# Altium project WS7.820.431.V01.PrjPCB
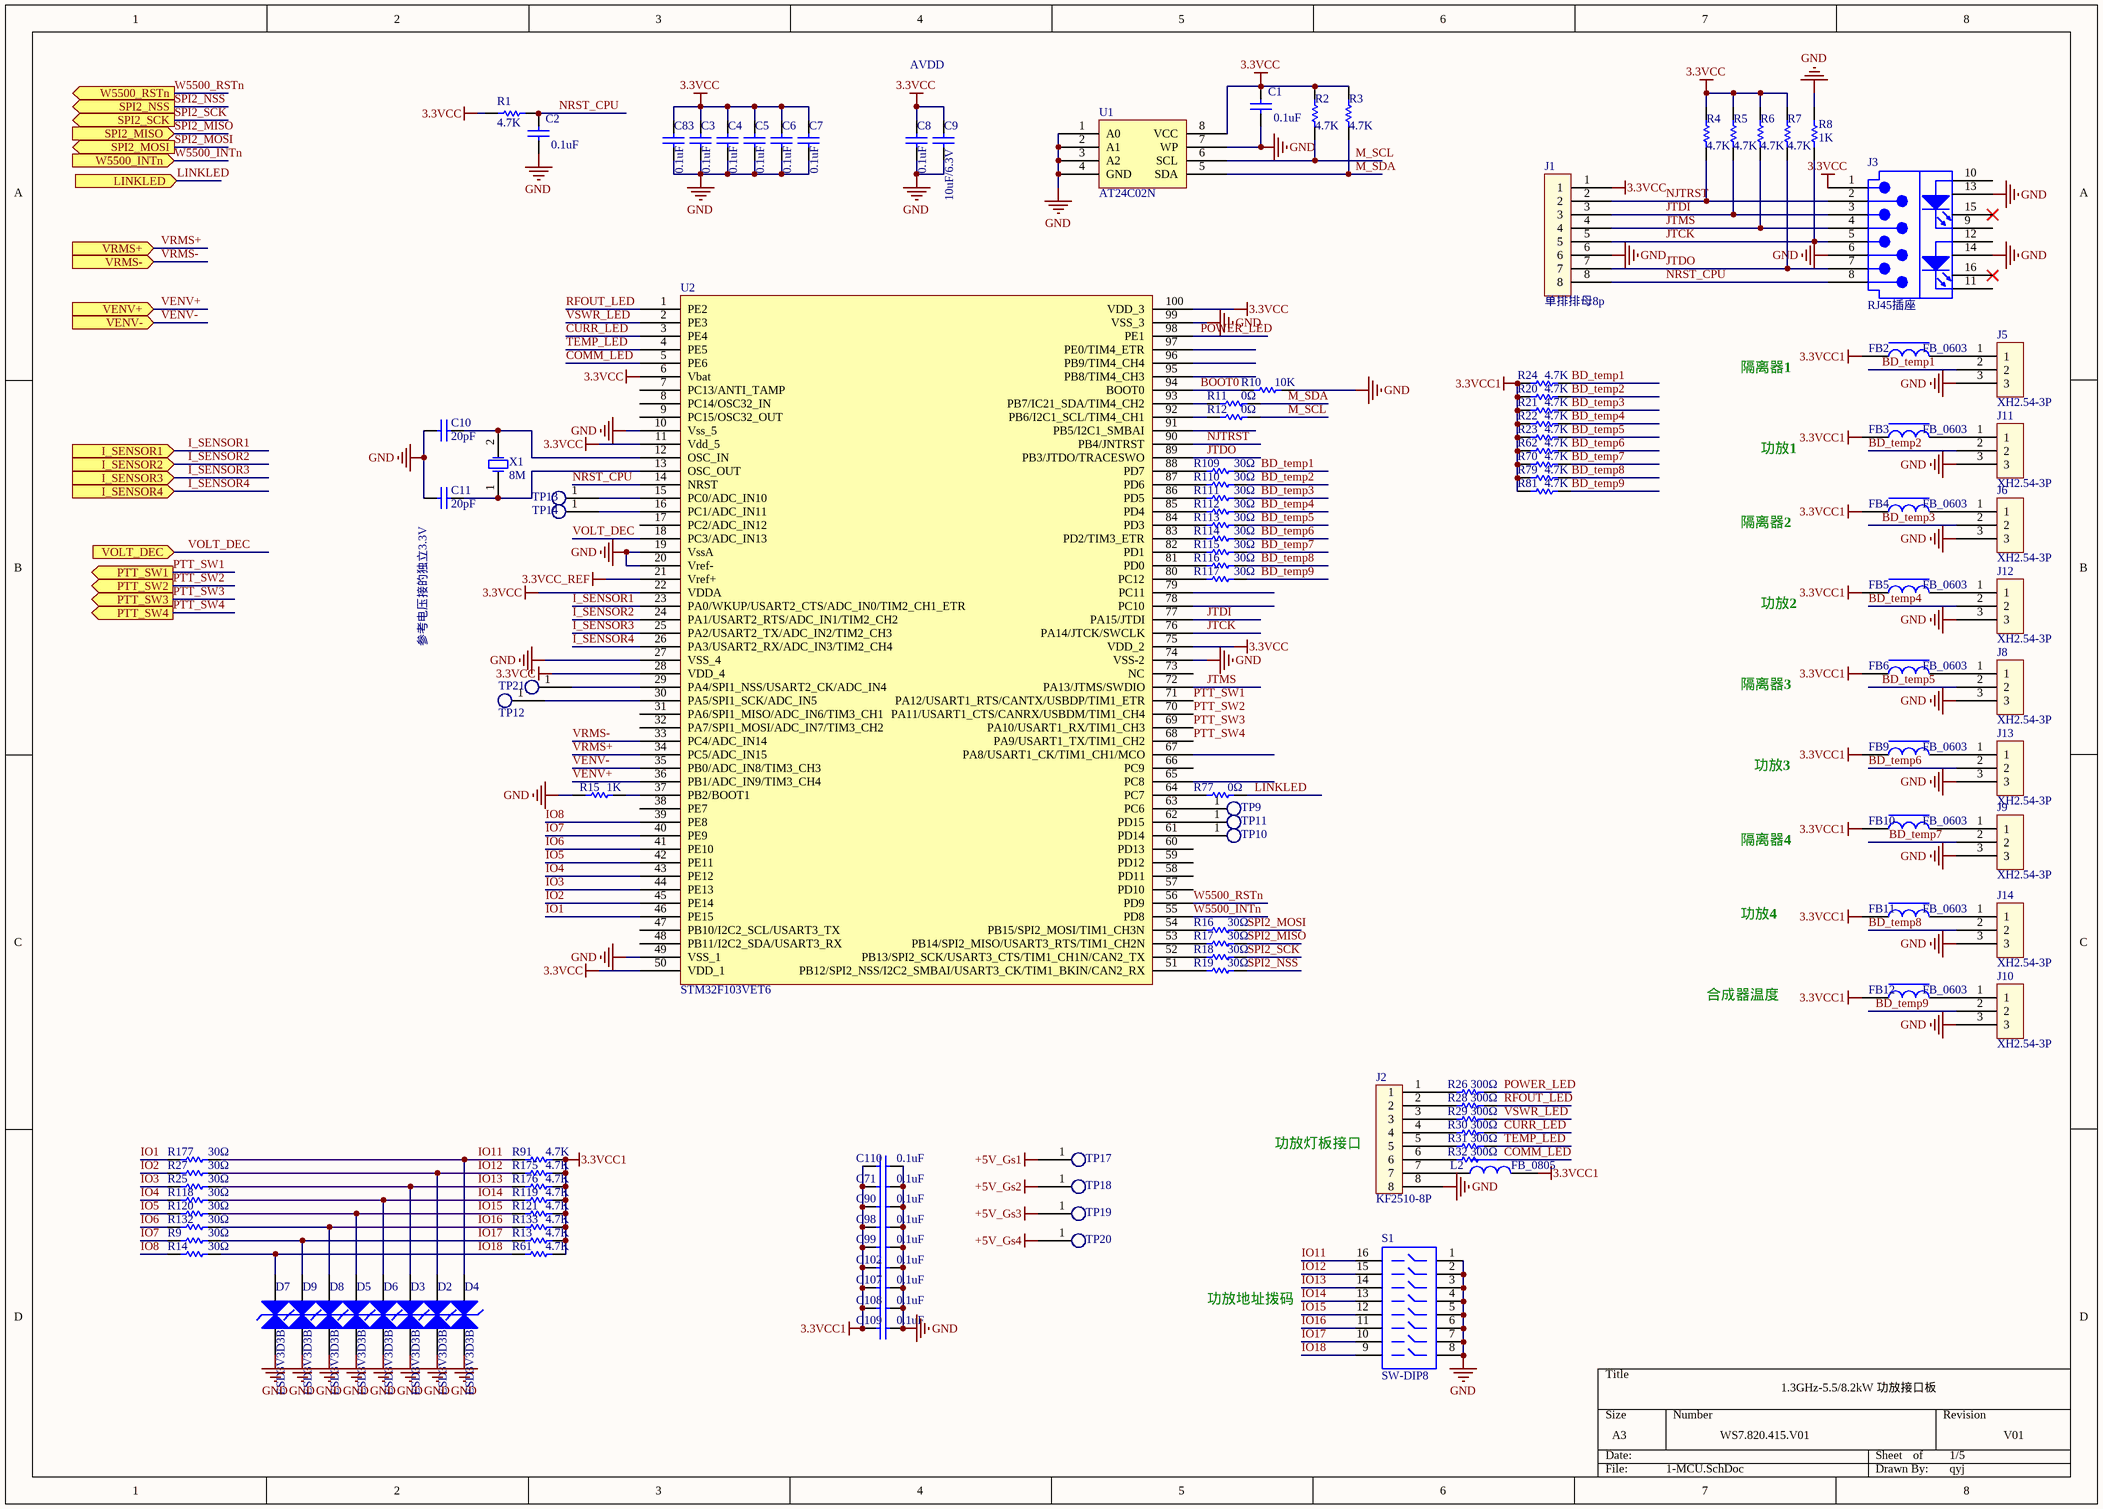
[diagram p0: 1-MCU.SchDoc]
4 sheets, 379 parts. Net scope: flat (ports and power ports of the same name join across sheets).
Board files: WS7.820.431.V01.PcbDoc, 功放插件尺寸图.PcbDoc
Sheets:
  1-MCU.SchDoc
  2-RJ45.SchDoc
  3-RF.SchDoc
  4-POWER.SchDoc

## Sheet 1-MCU.SchDoc
size A3

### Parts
C1  0.1uF  [C0603]
C2  0.1uF  [C0603]
C3  0.1uF  [C0603]
C4  0.1uF  [C0603]
C5  0.1uF  [C0603]
C6  0.1uF  [C0603]
C7  0.1uF  [C0603]
C8  0.1uF  [C0603]
C9  10uF/6.3V  [C0603]
C10  20pF  [C0603]
C11  20pF  [C0603]
C71  0.1uF  [C0603]
C83  0.1uF  [C0603]
C90  0.1uF  [C0603]
C98  0.1uF  [C0603]
C99  0.1uF  [C0603]
C102  0.1uF  [C0603]
C107  0.1uF  [C0603]
C108  0.1uF  [C0603]
C109  0.1uF  [C0603]
C110  0.1uF  [C0603]
D2  ESD3V3D3B  [SOD-323]
D3  ESD3V3D3B  [SOD-323]
D4  ESD3V3D3B  [SOD-323]
D5  ESD3V3D3B  [SOD-323]
D6  ESD3V3D3B  [SOD-323]
D7  ESD3V3D3B  [SOD-323]
D8  ESD3V3D3B  [SOD-323]
D9  ESD3V3D3B  [SOD-323]
FB2  FB_0603  [L0603]
FB3  FB_0603  [L0603]
FB4  FB_0603  [L0603]
FB5  FB_0603  [L0603]
FB6  FB_0603  [L0603]
FB9  FB_0603  [L0603]
FB10  FB_0603  [L0603]
FB11  FB_0603  [L0603]
FB12  FB_0603  [L0603]
J1  单排排母8p  [SIP8TM-2R54]
J2  KF2510-8P  [KF2510-8P -2R54-20R32x6R0-wanzhen]
J3  RJ45插座  [RJ45TH-1x1-2R54-LED]
J5  XH2.54-3P  [XH2.54mm-10R0x7R0--zhizhen]
J6  XH2.54-3P  [XH2.54mm-10R0x7R0--zhizhen]
J8  XH2.54-3P  [XH2.54mm-10R0x7R0--zhizhen]
J9  XH2.54-3P  [XH2.54mm-10R0x7R0--zhizhen]
J10  XH2.54-3P  [XH2.54mm-10R0x7R0--zhizhen]
J11  XH2.54-3P  [XH2.54mm-10R0x7R0--zhizhen]
J12  XH2.54-3P  [XH2.54mm-10R0x7R0--zhizhen]
J13  XH2.54-3P  [XH2.54mm-10R0x7R0--zhizhen]
J14  XH2.54-3P  [XH2.54mm-10R0x7R0--zhizhen]
L2  FB_0805  [L0805]
R1  4.7K  [R0603]
R2  4.7K  [R0603]
R3  4.7K  [R0603]
R4  4.7K  [R0603]
R5  4.7K  [R0603]
R6  4.7K  [R0603]
R7  4.7K  [R0603]
R8  1K  [R0603]
R9  30Ω  [R0603]
R10  10K  [R0603]
R11  0Ω  [R0603]
R12  0Ω  [R0603]
R13  4.7K  [R0603]
R14  30Ω  [R0603]
R15  1K  [R0603]
R16  30Ω  [R0603]
R17  30Ω  [R0603]
R18  30Ω  [R0603]
R19  30Ω  [R0603]
R20  4.7K  [R0603]
R21  4.7K  [R0603]
R22  4.7K  [R0603]
R23  4.7K  [R0603]
R24  4.7K  [R0603]
R25  30Ω  [R0603]
R26  300Ω  [R0603]
R27  30Ω  [R0603]
R28  300Ω  [R0603]
R29  300Ω  [R0603]
R30  300Ω  [R0603]
R31  300Ω  [R0603]
R32  300Ω  [R0603]
R61  4.7K  [R0603]
R62  4.7K  [R0603]
R70  4.7K  [R0603]
R77  0Ω  [R0603]
R79  4.7K  [R0603]
R81  4.7K  [R0603]
R91  4.7K  [R0603]
R109  30Ω  [R0603]
R110  30Ω  [R0603]
R111  30Ω  [R0603]
R112  30Ω  [R0603]
R113  30Ω  [R0603]
R114  30Ω  [R0603]
R115  30Ω  [R0603]
R116  30Ω  [R0603]
R117  30Ω  [R0603]
R118  30Ω  [R0603]
R119  4.7K  [R0603]
R120  30Ω  [R0603]
R121  4.7K  [R0603]
R132  30Ω  [R0603]
R133  4.7K  [R0603]
R175  4.7K  [R0603]
R176  4.7K  [R0603]
R177  30Ω  [R0603]
S1  SW-DIP8  [DIP-16-KEY]
TP9  TEST  [TP0R8]  (value not drawn)  (no BOM)
TP10  TEST  [TP0R8]  (value not drawn)  (no BOM)
TP11  TEST  [TP0R8]  (value not drawn)  (no BOM)
TP12  TEST  [TP0R8]  (value not drawn)  (no BOM)
TP13  TEST  [TP0R8]  (value not drawn)  (no BOM)
TP14  TEST  [TP0R8]  (value not drawn)  (no BOM)
TP17  (no value)  [TP2R54mm]  (no BOM)
TP18  (no value)  [TP2R54mm]  (no BOM)
TP19  (no value)  [TP2R54mm]  (no BOM)
TP20  (no value)  [TP2R54mm]  (no BOM)
TP21  TEST  [TP0R8]  (value not drawn)  (no BOM)
U1  AT24C02N  [SOIC8_1R27_3R9x4R9]
U2  STM32F103VET6  [LQFP100_0R5_14x14]
X1  8M  [CRY2SM-6R0x3R5]

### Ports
I_SENSOR1 (in), I_SENSOR2 (in), I_SENSOR3 (in), I_SENSOR4 (in), LINKLED (in), PTT_SW1 (out), PTT_SW2 (out), PTT_SW3 (out), PTT_SW4 (out), SPI2_MISO (in), SPI2_MOSI (out), SPI2_NSS (out), SPI2_SCK (out), VENV+ (in), VENV- (in), VOLT_DEC (in), VRMS+ (in), VRMS- (in), W5500_INTn (in), W5500_RSTn (out)

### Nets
3.3VCC: C1.2 C3.2 C4.2 C5.2 C6.2 C7.2 C8.2 C9.2 C83.2 J1.1 J3.1(TX+) R1.2 R2.2 R3.2 R4.2 R5.2 R6.2 R7.2 U1.8(VCC) U2.6(Vbat) U2.11(Vdd_5) U2.22(VDDA) U2.28(VDD_4) U2.50(VDD_1) U2.75(VDD_2) U2.100(VDD_3)
3.3VCC1: C71.1 C90.1 C98.1 C99.1 C102.1 C107.1 C108.1 C109.1 C110.1 FB2.1 FB3.1 FB4.1 FB5.1 FB6.1 FB9.1 FB10.1 FB11.1 FB12.1 L2.2 R13.1 R20.1 R21.1 R22.1 R23.1 R24.1 R61.1 R62.1 R70.1 R79.1 R81.1 R91.1 R119.1 R121.1 R133.1 R175.1 R176.1
3.3VCC_REF: U2.21(Vref+)
+5V_Gs1: TP17.1(TP)
+5V_Gs2: TP18.1(TP)
+5V_Gs3: TP19.1(TP)
+5V_Gs4: TP20.1(TP)
GND: C1.1 C2.1 C3.1 C4.1 C5.1 C6.1 C7.1 C8.1 C9.1 C10.2 C11.2 C71.2 C83.1 C90.2 C98.2 C99.2 C102.2 C107.2 C108.2 C109.2 C110.2 D2.2 D3.2 D4.2 D5.2 D6.2 D7.2 D8.2 D9.2 J1.6 J2.8 J3.6(RX-) J3.13 J3.14 J5.3 J6.3 J8.3 J9.3 J10.3 J11.3 J12.3 J13.3 J14.3 R8.1 R10.1 R15.1 S1.1 S1.2 S1.3 S1.4 S1.5 S1.6 S1.7 S1.8 U1.1(A0) U1.2(A1) U1.3(A2) U1.4(GND) U1.7(WP) U2.10(Vss_5) U2.19(VssA) U2.20(Vref-) U2.27(VSS_4) U2.49(VSS_1) U2.74(VSS-2) U2.99(VSS_3)
BD_temp1: J5.2 R24.2 R109.2
BD_temp2: J11.2 R20.2 R110.2
BD_temp3: J6.2 R21.2 R111.2
BD_temp4: J12.2 R22.2 R112.2
BD_temp5: J8.2 R23.2 R113.2
BD_temp6: J13.2 R62.2 R114.2
BD_temp7: J9.2 R70.2 R115.2
BD_temp8: J14.2 R79.2 R116.2
BD_temp9: J10.2 R81.2 R117.2
BOOT0: R10.2 U2.94(BOOT0)
COMM_LED: R32.2 U2.5(PE6)
CURR_LED: R30.2 U2.3(PE4)
I_SENSOR1: U2.23(PA0/WKUP/USART2_CTS/ADC_IN0/TIM2_CH1_ETR) ; port I_SENSOR1
I_SENSOR2: U2.24(PA1/USART2_RTS/ADC_IN1/TIM2_CH2) ; port I_SENSOR2
I_SENSOR3: U2.25(PA2/USART2_TX/ADC_IN2/TIM2_CH3) ; port I_SENSOR3
I_SENSOR4: U2.26(PA3/USART2_RX/ADC_IN3/TIM2_CH4) ; port I_SENSOR4
IO1: R177.2 U2.46(PE15)
IO2: R27.2 U2.45(PE14)
IO3: R25.2 U2.44(PE13)
IO4: R118.2 U2.43(PE12)
IO5: R120.2 U2.42(PE11)
IO6: R132.2 U2.41(PE10)
IO7: R9.2 U2.40(PE9)
IO8: R14.2 U2.39(PE8)
IO11: D4.1 R91.2 R177.1 S1.16
IO12: D2.1 R27.1 R175.2 S1.15
IO13: D3.1 R25.1 R176.2 S1.14
IO14: D6.1 R118.1 R119.2 S1.13
IO15: D5.1 R120.1 R121.2 S1.12
IO16: D8.1 R132.1 R133.2 S1.11
IO17: D9.1 R9.1 R13.2 S1.10
IO18: D7.1 R14.1 R61.2 S1.9
JTCK: J1.5 J3.5(NC) R8.2 U2.76(PA14/JTCK/SWCLK)
JTDI: J1.3 J3.3(RX+) R5.1 U2.77(PA15/JTDI)
JTDO: J1.7 J3.7(NC) R7.1 U2.89(PB3/JTDO/TRACESWO)
JTMS: J1.4 J3.4(NC) R6.1 U2.72(PA13/JTMS/SWDIO)
LINKLED: R77.2 ; port LINKLED
M_SCL: R2.1 R12.2 U1.6(SCL)
M_SDA: R3.1 R11.2 U1.5(SDA)
NJTRST: J1.2 J3.2(TX-) R4.1 U2.90(PB4/JNTRST)
NRST_CPU: C2.2 J1.8 J3.8(NC) R1.1 U2.14(NRST)
POWER_LED: R26.2 U2.98(PE1)
PTT_SW1: U2.71(PA12/USART1_RTS/CANTX/USBDP/TIM1_ETR) ; port PTT_SW1
PTT_SW2: U2.70(PA11/USART1_CTS/CANRX/USBDM/TIM1_CH4) ; port PTT_SW2
PTT_SW3: U2.69(PA10/USART1_RX/TIM1_CH3) ; port PTT_SW3
PTT_SW4: U2.68(PA9/USART1_TX/TIM1_CH2) ; port PTT_SW4
RFOUT_LED: R28.2 U2.1(PE2)
SPI2_MISO: R17.2 ; port SPI2_MISO
SPI2_MOSI: R16.2 ; port SPI2_MOSI
SPI2_NSS: R19.2 ; port SPI2_NSS
SPI2_SCK: R18.2 ; port SPI2_SCK
TEMP_LED: R31.2 U2.4(PE5)
VENV+: U2.36(PB1/ADC_IN9/TIM3_CH4) ; port VENV+
VENV-: U2.35(PB0/ADC_IN8/TIM3_CH3) ; port VENV-
VOLT_DEC: U2.18(PC3/ADC_IN13) ; port VOLT_DEC
VRMS+: U2.34(PC5/ADC_IN15) ; port VRMS+
VRMS-: U2.33(PC4/ADC_IN14) ; port VRMS-
VSWR_LED: R29.2 U2.2(PE3)
W5500_INTn: U2.55(PD8) ; port W5500_INTn
W5500_RSTn: U2.56(PD9) ; port W5500_RSTn
NetC10_1: C10.1 U2.12(OSC_IN) X1.2(OSC2)
NetC11_1: C11.1 U2.13(OSC_OUT) X1.1(OSC1)
NetFB2_2: FB2.2 J5.1
NetFB3_2: FB3.2 J11.1
NetFB4_2: FB4.2 J6.1
NetFB5_2: FB5.2 J12.1
NetFB6_2: FB6.2 J8.1
NetFB9_2: FB9.2 J13.1
NetFB10_2: FB10.2 J9.1
NetFB11_2: FB11.2 J14.1
NetFB12_2: FB12.2 J10.1
NetJ2_1: J2.1 R26.1
NetJ2_2: J2.2 R28.1
NetJ2_3: J2.3 R29.1
NetJ2_4: J2.4 R30.1
NetJ2_5: J2.5 R31.1
NetJ2_6: J2.6 R32.1
NetJ2_7: J2.7 L2.1
NetR11_1: R11.1 U2.93(PB7/IC21_SDA/TIM4_CH2)
NetR12_1: R12.1 U2.92(PB6/I2C1_SCL/TIM4_CH1)
NetR15_2: R15.2 U2.37(PB2/BOOT1)
NetR16_1: R16.1 U2.54(PB15/SPI2_MOSI/TIM1_CH3N)
NetR17_1: R17.1 U2.53(PB14/SPI2_MISO/USART3_RTS/TIM1_CH2N)
NetR18_1: R18.1 U2.52(PB13/SPI2_SCK/USART3_CTS/TIM1_CH1N/CAN2_TX)
NetR19_1: R19.1 U2.51(PB12/SPI2_NSS/I2C2_SMBAI/USART3_CK/TIM1_BKIN/CAN2_RX)
NetR77_1: R77.1 U2.64(PC7)
NetR109_1: R109.1 U2.88(PD7)
NetR110_1: R110.1 U2.87(PD6)
NetR111_1: R111.1 U2.86(PD5)
NetR112_1: R112.1 U2.85(PD4)
NetR113_1: R113.1 U2.84(PD3)
NetR114_1: R114.1 U2.83(PD2/TIM3_ETR)
NetR115_1: R115.1 U2.82(PD1)
NetR116_1: R116.1 U2.81(PD0)
NetR117_1: R117.1 U2.80(PC12)
NetTP9_1: TP9.1(TP) U2.63(PC6)
NetTP10_1: TP10.1(TP) U2.61(PD14)
NetTP11_1: TP11.1(TP) U2.62(PD15)
NetTP12_1: TP12.1(TP) U2.30(PA5/SPI1_SCK/ADC_IN5)
NetTP13_1: TP13.1(TP) U2.15(PC0/ADC_IN10)
NetTP14_1: TP14.1(TP) U2.16(PC1/ADC_IN11)
NetTP21_1: TP21.1(TP) U2.29(PA4/SPI1_NSS/USART2_CK/ADC_IN4)

Not connected (* = marked no-connect by the designer): J3 9(K1) 10(A1) 11(K2) 12(A2) 15* 16*; U2 7(PC13/ANTI_TAMP) 8(PC14/OSC32_IN) 9(PC15/OSC32_OUT) 17(PC2/ADC_IN12) 31(PA6/SPI1_MISO/ADC_IN6/TIM3_CH1) 32(PA7/SPI1_MOSI/ADC_IN7/TIM3_CH2) 38(PE7) 47(PB10/I2C2_SCL/USART3_TX) 48(PB11/I2C2_SDA/USART3_RX) 57(PD10) 58(PD11) 59(PD12) 60(PD13) 65(PC8) 66(PC9) 67(PA8/USART1_CK/TIM1_CH1/MCO) 73(NC) 78(PC10) 79(PC11) 91(PB5/I2C1_SMBAI) 95(PB8/TIM4_CH3) 96(PB9/TIM4_CH4) 97(PE0/TIM4_ETR)

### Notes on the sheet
- AVDD
- 隔离器1
- 功放1
- 隔离器2
- 参考电压接的独立3.3V
- 功放2
- 隔离器3
- 功放3
- 隔离器4
- 功放4
- 合成器温度
- 功放灯板接口
- 功放地址拨码
- 1.3GHz-5.5/8.2kW 功放接口板
- WS7.820.415.V01
- 1/5
- V01
- qyj

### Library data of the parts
C1-C8 C83 = 0.1uF贴片电容: 贴片电容_GRM188R71H104KA01D_0.1uF±10%,50V,0603; code: 01010045
C9 = 10uF贴片电容: 贴片电容_GRM188R60J106ME47D_10uF±20%,6.3V,0603; code: 01010037
C10 C11 = 20pF贴片电容: 贴片电容_GRM188C1H200JB01D_20pF±5%,50V,0603; code: 01010035
C71 C90 C98 C99 C102 C107-C110 = 0.1uF: GRM188R71H104KA01D; MPN: MURATA; WSPN: 01010045
D2-D9 = ESD5B5.0ST1G: ESD_ESD3V3D3B_SOD-323,3.3V,双管
FB2-FB6 FB9-FB12 = 0603贴片磁珠: 贴片磁珠_100R,0603; code: 0103016
J1 = 8p-2.54单排母座: 连接器_单排排母座8p_直插,间距2.54mm; MPN: WS; code: 01090052
J2 = KF2510-8P弯针: 连接器_KF2510-8P_90°弯针,间距2.54mm
J3 = RJ45弯脚带灯: RJ45插座_1*1,带左黄右绿灯,弯脚; MPN: 朱迅; code: 01090042
J5 J6 J8-J14 = XH2.54-3P: 连接器_XH2.54-3P_弯针,间距2.54mm
L2 = 0805贴片磁珠: 贴片磁珠_600R,0805; code: 01030023
R1-R7 R13 R20-R24 R61 R62 R70 R79 R81 R91 R119 R121 R133 R175 R176 = 4.7K贴片电阻: 贴片电阻_4.7K±5%,0603; code: 01020012
R8 R15 = 1K贴片电阻: 贴片电阻_1K±5%,0603; code: 01020082
R9 R14 R25 R27 R118 R120 R132 R177 = 0Ω贴片电阻: 贴片电阻_30Ω±5%,0603; code: 01020010
R10 = 10K贴片电阻: 贴片电阻_10K±5%,0603; code: 01020011
R11 R12 R77 = 0Ω贴片电阻: 贴片电阻_0Ω±5%,0603; code: 01020010
R16-R19 R109-R117 = 30Ω贴片电阻: 贴片电阻_30Ω±5%,0603; code: 01020108
R26 R28-R32 = 300Ω贴片电阻: 贴片电阻_300Ω±5%,0603; code: 01020008
S1 = SW-DIP8: 4009 Series DIP Switch, Raised actuator
TP9-TP14 TP21 = TP0.8mm: 表贴测试点0.8mm
TP17-TP20 = TP2mm: 表贴测试点1mm
U1 = AT24C02N: EEPROM_AT24C02N_SOIC8; Maker: ATMEL; code: 01060068
U2 = STM32F103VET: MCU_STM32F103VET6_32 bit, LQFP100; Maker: ST; code: 01060037
X1 = 8M贴片无源晶体: 贴片无源晶体_8MHz,封装6035; code: 03050006

## Sheet 2-RJ45.SchDoc
size A3
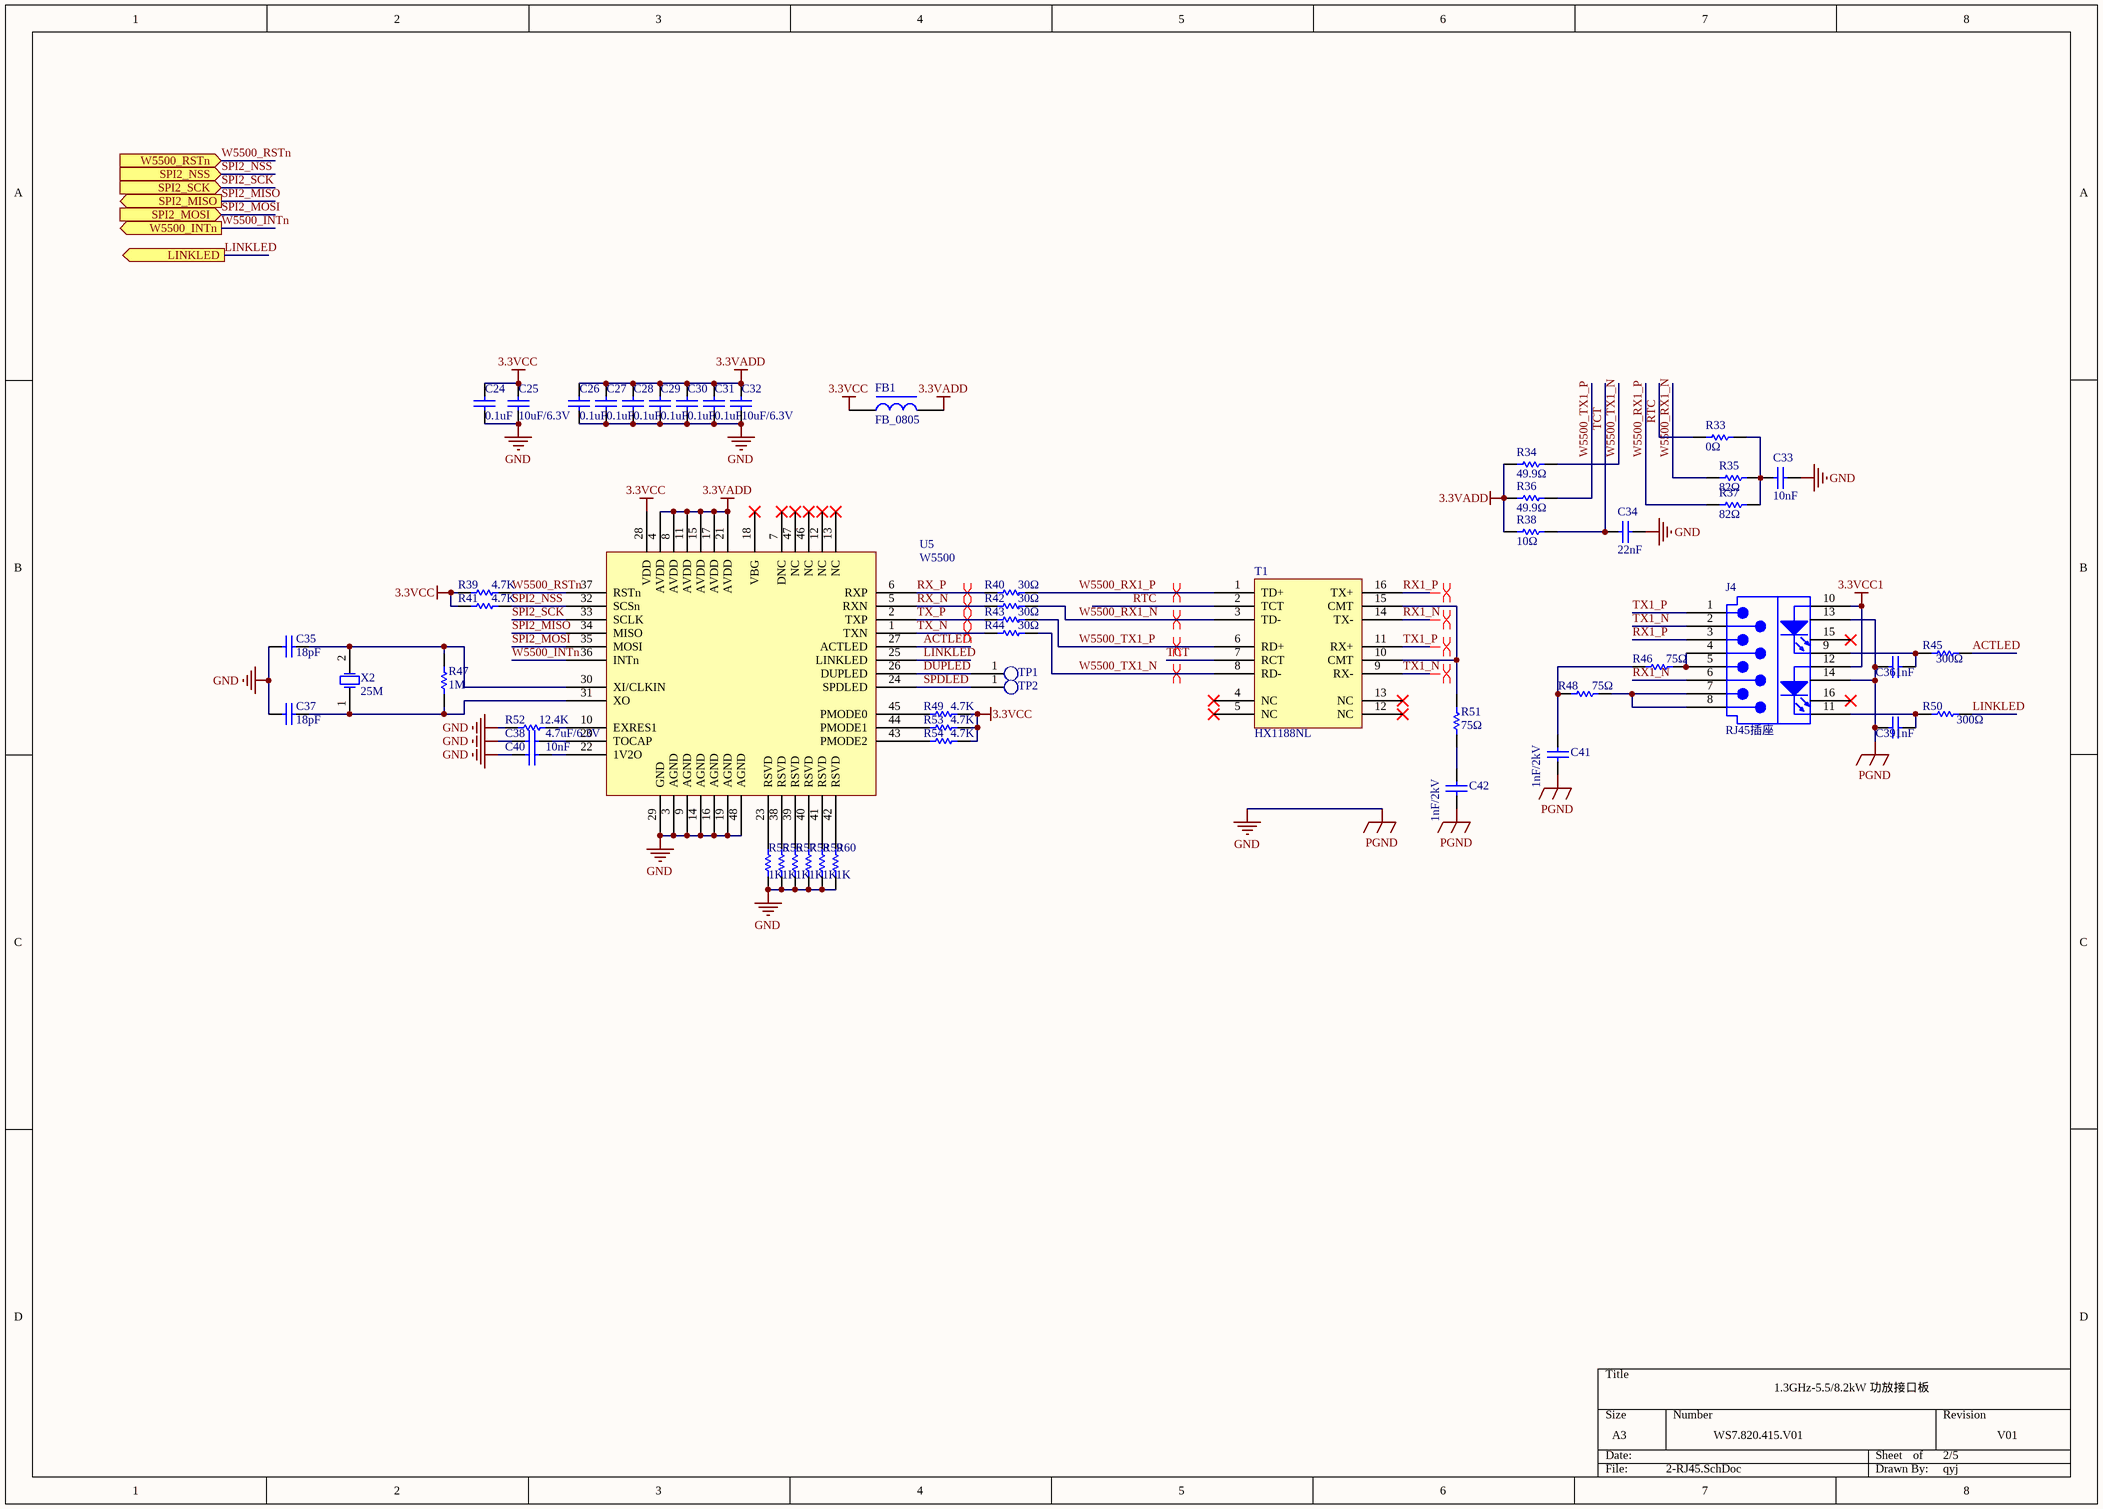
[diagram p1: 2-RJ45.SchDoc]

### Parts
C24  0.1uF  [C0603]
C25  10uF/6.3V  [C0603]
C26  0.1uF  [C0603]
C27  0.1uF  [C0603]
C28  0.1uF  [C0603]
C29  0.1uF  [C0603]
C30  0.1uF  [C0603]
C31  0.1uF  [C0603]
C32  10uF/6.3V  [C0603]
C33  10nF  [C0603]
C34  22nF  [C0603]
C35  18pF  [C0603]
C36  1nF  [C0603]
C37  18pF  [C0603]
C38  4.7uF/6.3V  [C0603]
C39  1nF  [C0603]
C40  10nF  [C0603]
C41  1nF/2kV  [C1206]
C42  1nF/2kV  [C1206]
FB1  FB_0805  [L0805]
J4  RJ45插座  [RJ45TH-1x1-2R54-LED]
R33  0Ω  [R0603]
R34  49.9Ω  [R0603]
R35  82Ω  [R0603]
R36  49.9Ω  [R0603]
R37  82Ω  [R0603]
R38  10Ω  [R0603]
R39  4.7K  [R0603]
R40  30Ω  [R0603]
R41  4.7K  [R0603]
R42  30Ω  [R0603]
R43  30Ω  [R0603]
R44  30Ω  [R0603]
R45  300Ω  [R0603]
R46  75Ω  [R0805]
R47  1M  [R0603]
R48  75Ω  [R0805]
R49  4.7K  [R0603]
R50  300Ω  [R0603]
R51  75Ω  [R1206]
R52  12.4K  [R0603]
R53  4.7K  [R0603]
R54  4.7K  [R0603]
R55  1K  [R0603]
R56  1K  [R0603]
R57  1K  [R0603]
R58  1K  [R0603]
R59  1K  [R0603]
R60  1K  [R0603]
T1  HX1188NL  [SOP16-1R27-7R11x12R7]
TP1  TEST  [TP0R8]  (value not drawn)  (no BOM)
TP2  TEST  [TP0R8]  (value not drawn)  (no BOM)
U5  W5500  [TQFN48-0R5-7X7]
X2  25M  [CRY2SM-6R0x3R5]

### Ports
LINKLED (out), SPI2_MISO (out), SPI2_MOSI (in), SPI2_NSS (in), SPI2_SCK (in), W5500_INTn (out), W5500_RSTn (in)

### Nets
3.3VADD: C26.2 C27.2 C28.2 C29.2 C30.2 C31.2 C32.2 FB1.2 R34.2 R36.2 R38.2 U5.4(AVDD) U5.8(AVDD) U5.11(AVDD) U5.15(AVDD) U5.17(AVDD) U5.21(AVDD)
3.3VCC: C24.2 C25.2 FB1.1 R39.2 R41.2 R49.2 R53.2 R54.2 U5.28(VDD)
3.3VCC1: J4.10(A1) J4.12(A2)
GND: C24.1 C25.1 C26.1 C27.1 C28.1 C29.1 C30.1 C31.1 C32.1 C33.1 C34.1 C35.1 C36.1 C37.1 C38.1 C39.1 C40.1 C41.1 C42.1 J4.13 J4.14 R52.1 R55.1 R56.1 R57.1 R58.1 R59.1 R60.1 U5.3(AGND) U5.9(AGND) U5.14(AGND) U5.16(AGND) U5.19(AGND) U5.29(GND) U5.48(AGND)  [also labelled PGND]
ACTLED: R45.2 U5.27(ACTLED)
DUPLED: TP1.1(TP) U5.26(DUPLED)
LINKLED: R50.2 U5.25(LINKLED) ; port LINKLED
RTC: R33.2 T1.2(TCT)
RX1_N: J4.6(RX-) T1.14(TX-)
RX1_P: J4.3(RX+) T1.16(TX+)
RX_N: R42.1 U5.5(RXN)
RX_P: R40.1 U5.6(RXP)
SPDLED: TP2.1(TP) U5.24(SPDLED)
SPI2_MISO: U5.34(MISO) ; port SPI2_MISO
SPI2_MOSI: U5.35(MOSI) ; port SPI2_MOSI
SPI2_NSS: R41.1 U5.32(SCSn) ; port SPI2_NSS
SPI2_SCK: U5.33(SCLK) ; port SPI2_SCK
TCT: C34.2 R38.1 T1.7(RCT)
TX1_N: J4.2(TX-) T1.9(RX-)
TX1_P: J4.1(TX+) T1.11(RX+)
TX_N: R44.1 U5.1(TXN)
TX_P: R43.1 U5.2(TXP)
W5500_INTn: U5.36(INTn) ; port W5500_INTn
W5500_RSTn: R39.1 U5.37(RSTn) ; port W5500_RSTn
W5500_RX1_N: R35.2 R42.2 T1.3(TD-)
W5500_RX1_P: R37.2 R40.2 T1.1(TD+)
W5500_TX1_N: R34.1 R44.2 T1.8(RD-)
W5500_TX1_P: R36.1 R43.2 T1.6(RD+)
NetC33_2: C33.2 R33.1 R35.1 R37.1
NetC35_2: C35.2 R47.2 U5.30(XI/CLKIN) X2.2(OSC2)
NetC36_2: C36.2 J4.9(K1) R45.1
NetC37_2: C37.2 R47.1 U5.31(XO) X2.1(OSC1)
NetC38_2: C38.2 U5.20(TOCAP)
NetC39_2: C39.2 J4.11(K2) R50.1
NetC40_2: C40.2 U5.22(1V2O)
NetC41_2: C41.2 R46.1 R48.1
NetC42_2: C42.2 R51.1
NetJ4_4: J4.4(NC) J4.5(NC) R46.2
NetJ4_7: J4.7(NC) J4.8(NC) R48.2
NetR49_1: R49.1 U5.45(PMODE0)
NetR51_2: R51.2 T1.10(CMT) T1.15(CMT)
NetR52_2: R52.2 U5.10(EXRES1)
NetR53_1: R53.1 U5.44(PMODE1)
NetR54_1: R54.1 U5.43(PMODE2)
NetR55_2: R55.2 U5.23(RSVD)
NetR56_2: R56.2 U5.38(RSVD)
NetR57_2: R57.2 U5.39(RSVD)
NetR58_2: R58.2 U5.40(RSVD)
NetR59_2: R59.2 U5.41(RSVD)
NetR60_2: R60.2 U5.42(RSVD)

Not connected (* = marked no-connect by the designer): J4 15* 16*; T1 4(NC)* 5(NC)* 12(NC)* 13(NC)*; U5 7(DNC)* 12(NC)* 13(NC)* 18(VBG)* 46(NC)* 47(NC)*

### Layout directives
differential pair: RX1_N, RX1_P, RX_N, RX_P, TX1_N, TX1_P, TX_N, TX_P, W5500_RX1_N, W5500_RX1_P, W5500_TX1_N, W5500_TX1_P

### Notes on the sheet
- 1.3GHz-5.5/8.2kW 功放接口板
- WS7.820.415.V01
- 2/5
- V01
- qyj

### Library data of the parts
C24 C26-C31 = 0.1uF贴片电容: as C1 on sheet 1-MCU
C25 C32 = 10uF贴片电容: as C9 on sheet 1-MCU
C33 C40 = 0.1uF贴片电容: C0603C103K5RAC_10nF±10%,50V,0603; MPN: KEMET; code: 01010218
C34 = 27nF贴片电容: 贴片电容_22nF±5%,50V,0603; code: 01010054
C35 C37 = 18pF贴片电容: 贴片电容_GRM1885C1H180JA01D_18pF±5%,50V,0603; code: 01010102
C36 C39 = 1000pF贴片电容: 贴片电容_GRM188R71H102KA01_1000pF±10%,50V,0603; code: 01010093
C38 = 1uF贴片电容: GRM188R61C475K_4.7uF±10%,16V,0603; MPN: Murata; code: 01010098
C41 C42 = 10uF贴片电容: 贴片电容_C1206C102J5GAC _1000pF±5%,50V,1206; MPN: KEMET; code: 01010213
FB1 = 0805贴片磁珠: 贴片磁珠_600R,0805; code: 01030023
J4 = RJ45弯脚带灯: as J3 on sheet 1-MCU
R33 = 0Ω贴片电阻: 贴片电阻_0Ω±5%,0603; code: 01020010
R34 R36 = 51Ω贴片电阻: 贴片电阻_49.9Ω±1%,0603; code: 01020126
R35 R37 = 51Ω贴片电阻: 贴片电阻_82Ω±1%,0603; code: 01020196
R38 = 10Ω贴片电阻: 贴片电阻_10Ω±5%,0603; code: 01020104
R39 R41 R49 R53 R54 = 4.7K贴片电阻: 贴片电阻_4.7K±5%,0603; code: 01020012
R40 R42-R44 = 30Ω贴片电阻: 贴片电阻_30Ω±5%,0603; code: 01020108
R45 R50 = 300Ω贴片电阻: 贴片电阻_300Ω±5%,0603; code: 01020008
R46 R48 = 75Ω贴片电阻: 贴片电阻_75Ω±5%,0805; code: 01020068
R47 = 1M贴片电阻: 贴片电阻_1M±5%,0603; code: 01020093
R51 = 75Ω贴片电阻: 贴片电阻_75Ω±5%,1206; code: 01020197
R52 = 12K贴片电阻: 贴片电阻_12.4K±1%,0603
R55-R60 = 1K贴片电阻: 贴片电阻_1K±5%,0603; code: 01020082
T1 = HX1188NL: 网络变压器_HX1188NL_百兆,SOIC16; code: 01060114
TP1 TP2 = TP0.8mm: 表贴测试点0.8mm
U5 = W5500: 以太网控制器_W5500_LQFP48; code: 01060113
X2 = 25M贴片无源晶体: 贴片无源晶体_25MHz,30ppm,6035封装; code: 03050012

## Sheet 3-RF.SchDoc
size A2
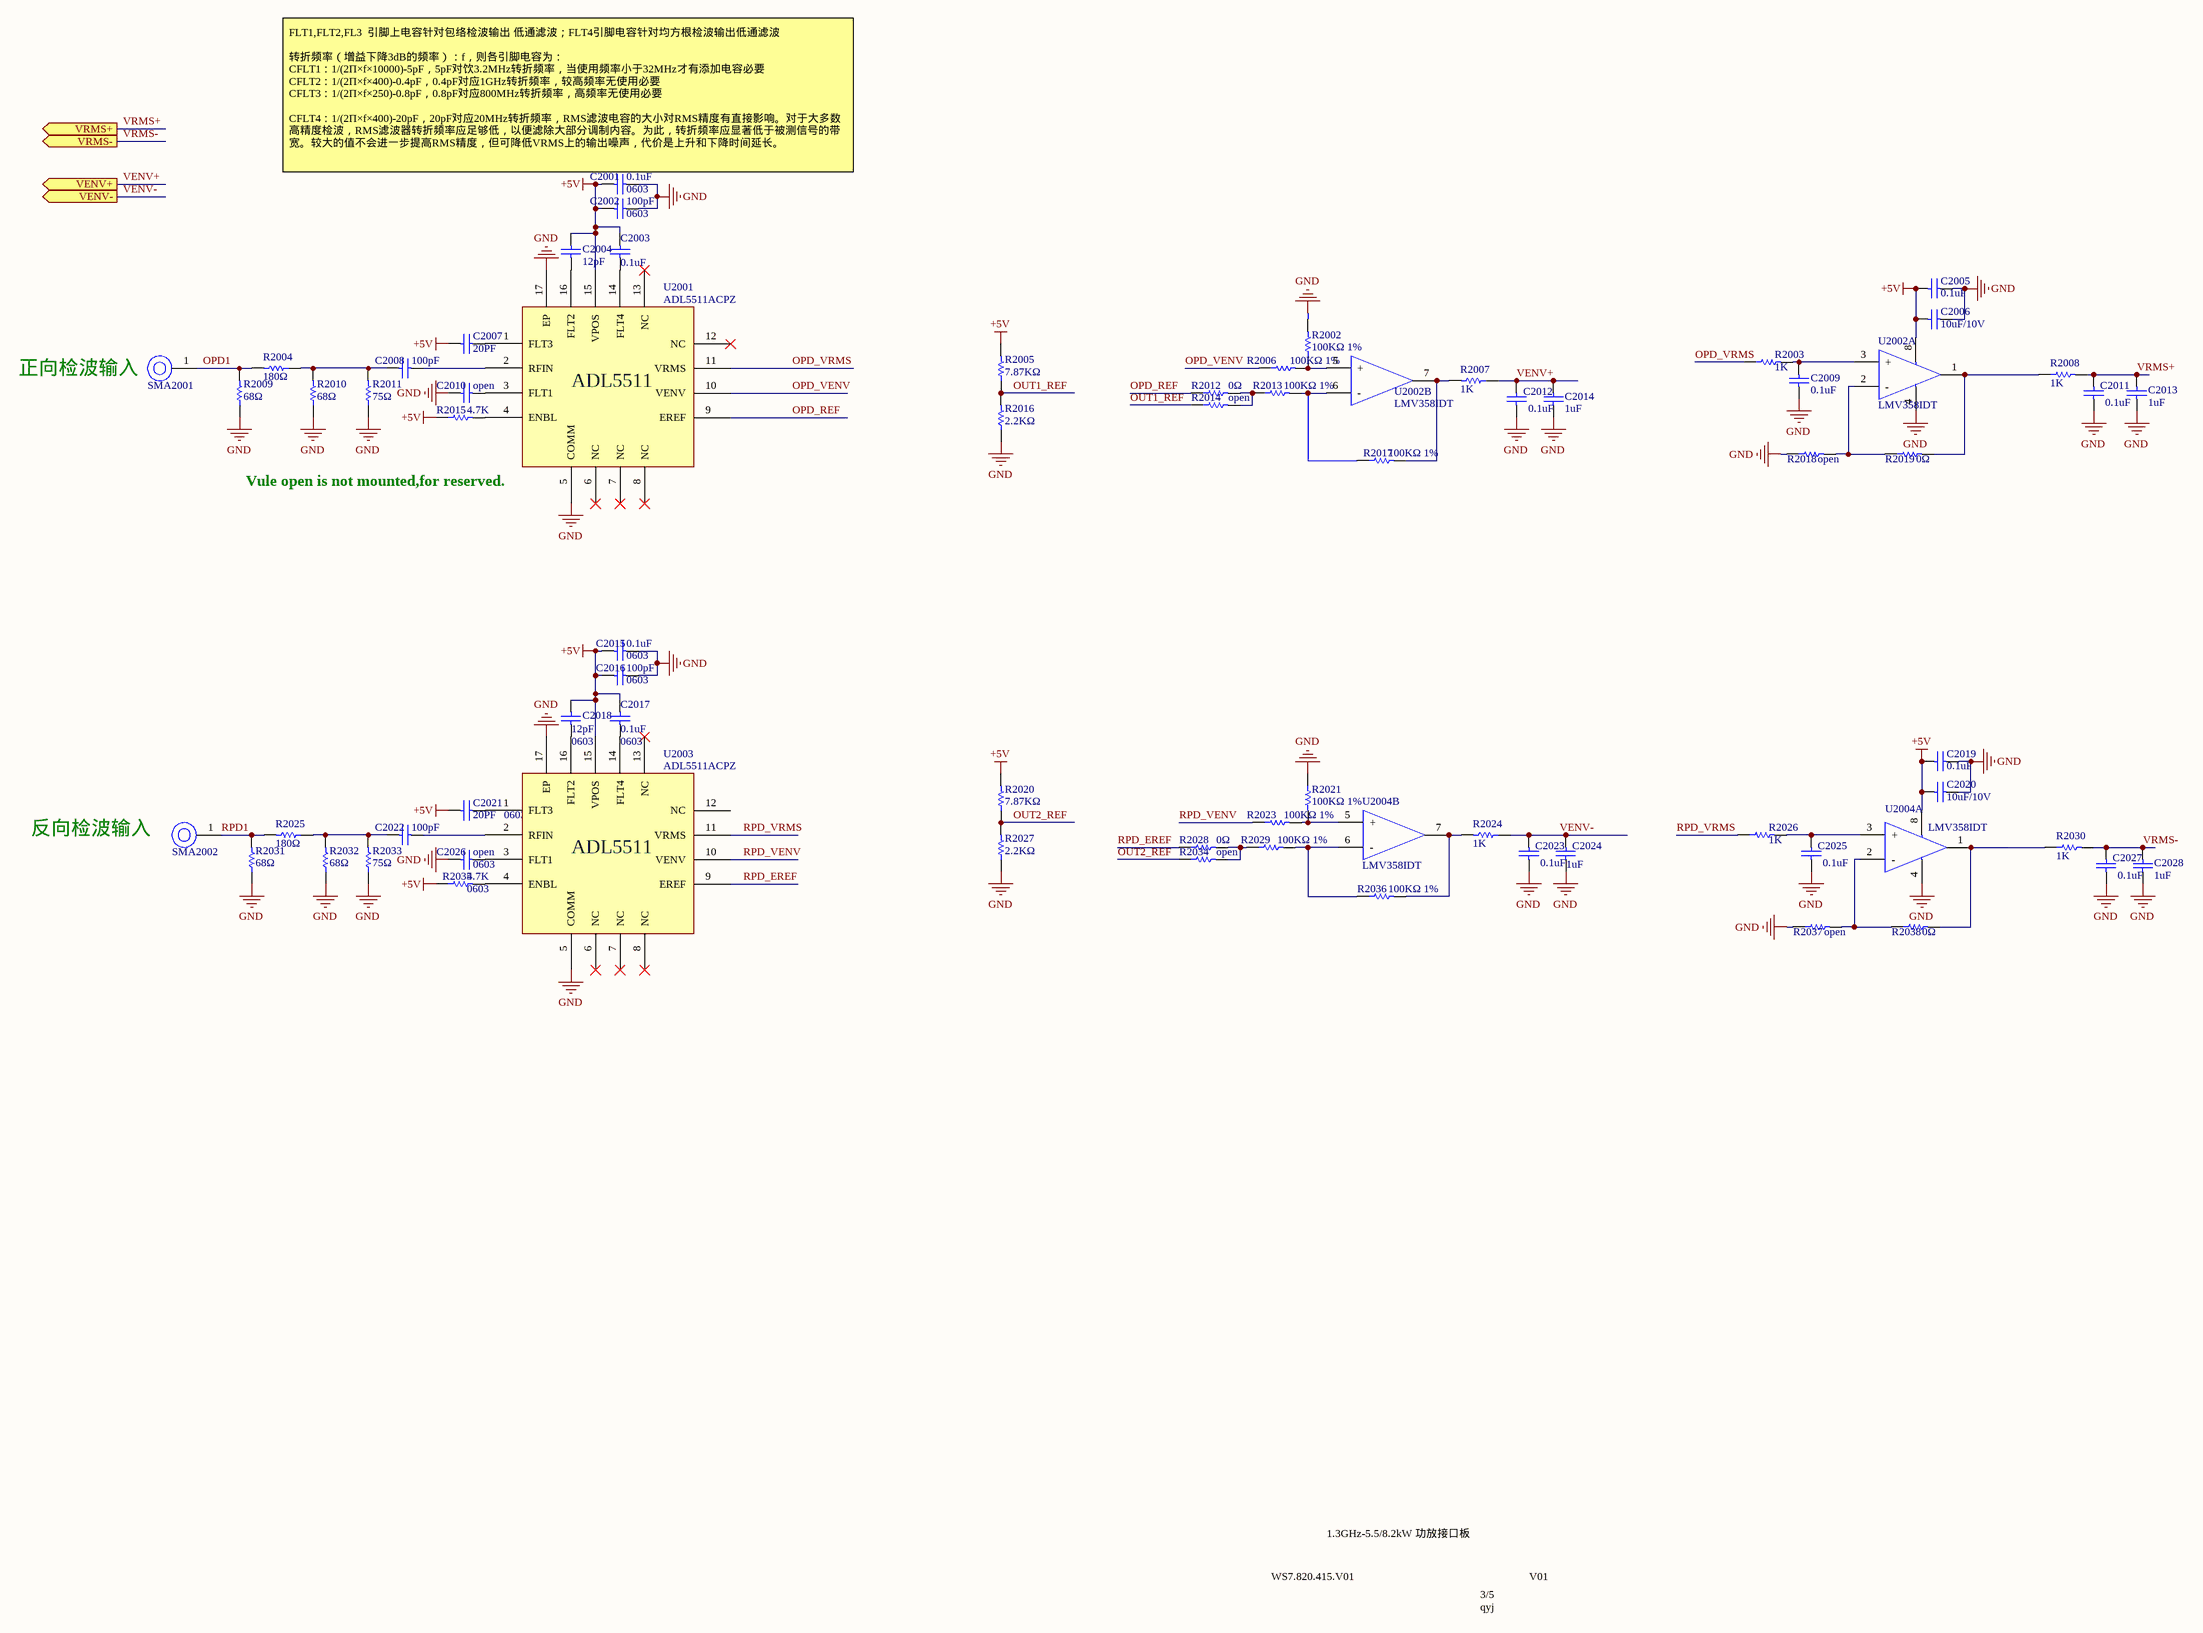
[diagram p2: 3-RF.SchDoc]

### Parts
C2001  0.1uF  [C0603]
C2002  100pF  [C0603]
C2003  0.1uF  [C0603]
C2004  12pF  [C0603]
C2005  0.1uF  [C0603]
C2006  10uF/10V  [C0805]
C2007  20PF  [C0603]
C2008  100pF  [C0805]
C2009  0.1uF  [C0603]
C2010  open  [C0603]  (no BOM)
C2011  0.1uF  [C0603]
C2012  0.1uF  [C0603]
C2013  1uF  [C0603]
C2014  1uF  [C0603]
C2015  0.1uF  [C0603]
C2016  100pF  [C0603]
C2017  0.1uF  [C0603]
C2018  12pF  [C0603]
C2019  0.1uF  [C0603]
C2020  10uF/10V  [C0805]
C2021  20PF  [C0603]
C2022  100pF  [C0805]
C2023  0.1uF  [C0603]
C2024  1uF  [C0603]
C2025  0.1uF  [C0603]
C2026  open  [C0603]  (no BOM)
C2027  0.1uF  [C0603]
C2028  1uF  [C0603]
R2002  100KΩ 1%  [R0603]
R2003  1K  [R0603]
R2004  180Ω  [R1206]
R2005  7.87KΩ  [R0603]  (no BOM)
R2006  100KΩ 1%  [R0603]
R2007  1K  [R0603]
R2008  1K  [R0603]
R2009  68Ω  [R1206]
R2010  68Ω  [R1206]
R2011  75Ω  [R0805]
R2012  0Ω  [R0603]
R2013  100KΩ 1%  [R0603]
R2014  open  [R0603]  (no BOM)
R2015  4.7K  [R0603]
R2016  2.2KΩ  [R0603]  (no BOM)
R2017  100KΩ 1%  [R0603]
R2018  open  [R0603]  (no BOM)
R2019  0Ω  [R0603]
R2020  7.87KΩ  [R0603]  (no BOM)
R2021  100KΩ 1%  [R0603]
R2023  100KΩ 1%  [R0603]
R2024  1K  [R0603]
R2025  180Ω  [R1206]
R2026  1K  [R0603]
R2027  2.2KΩ  [R0603]  (no BOM)
R2028  0Ω  [R0603]
R2029  100KΩ 1%  [R0603]
R2030  1K  [R0603]
R2031  68Ω  [R1206]
R2032  68Ω  [R1206]
R2033  75Ω  [R0805]
R2034  open  [R0603]  (no BOM)
R2035  4.7K  [R0603]
R2036  100KΩ 1%  [R0603]
R2037  open  [R0603]  (no BOM)
R2038  0Ω  [R0603]
SMA2001  SMA-KFD-4  [SMA-50KFD-4]  (value not drawn)  (no BOM)
SMA2002  SMA-KFD-4  [SMA-50KFD-4]  (value not drawn)  (no BOM)
U2001  ADL5511ACPZ  [QFN16_0R50_3X3]
U2002  LMV358IDT  [SOIC8_1R27_3R9x4R9]  (parts A,B of 2)
U2003  ADL5511ACPZ  [QFN16_0R50_3X3]
U2004  LMV358IDT  [SOIC8_1R27_3R9x4R9]  (parts A,B of 2)

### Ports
VENV+ (out), VENV- (out), VRMS+ (out), VRMS- (out)

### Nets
+5V: C2001.2 C2002.1 C2003.2 C2004.2 C2005.1 C2006.1 C2007.1 C2015.2 C2016.1 C2017.2 C2018.2 C2019.1 C2020.1 C2021.1 R2005.2 R2015.1 R2020.2 R2035.1 U2001.15(VPOS) U2002.8 U2003.15(VPOS) U2004.8
GND: C2001.1 C2002.2 C2005.2 C2006.2 C2009.1 C2010.1 C2011.1 C2012.1 C2013.1 C2014.1 C2015.1 C2016.2 C2019.2 C2020.2 C2023.1 C2024.1 C2025.1 C2026.1 C2027.1 C2028.1 R2002.2 R2009.1 R2010.1 R2011.1 R2016.1 R2018.1 R2021.1 R2027.1 R2031.1 R2032.1 R2033.1 R2037.1 U2001.5(COMM) U2001.17(EP) U2002.4 U2003.5(COMM) U2003.17(EP) U2004.4
OPD1: R2004.2 R2009.2 SMA2001.1(Sig)
OPD_REF: R2012.1 U2001.9(EREF)
OPD_VENV: R2006.1 U2001.10(VENV)
OPD_VRMS: R2003.1 U2001.11(VRMS)
OUT1_REF: R2005.1 R2014.1 R2016.2
OUT2_REF: R2020.1 R2027.2 R2034.1
RPD1: R2025.2 R2031.2 SMA2002.1(Sig)
RPD_EREF: R2028.1 U2003.9(EREF)
RPD_VENV: R2023.1 U2003.10(VENV)
RPD_VRMS: R2026.1 U2003.11(VRMS)
VENV+: C2012.2 C2014.2 R2007.1 ; port VENV+
VENV-: C2023.2 C2024.2 R2024.1 ; port VENV-
VRMS+: C2011.2 C2013.2 R2008.2 ; port VRMS+
VRMS-: C2027.2 C2028.2 R2030.2 ; port VRMS-
NetC2003_1: C2003.1 U2001.14(FLT4)
NetC2004_1: C2004.1 U2001.16(FLT2)
NetC2007_2: C2007.2 U2001.1(FLT3)
NetC2008_1: C2008.1 R2004.1 R2010.2 R2011.2
NetC2008_2: C2008.2 U2001.2(RFIN)
NetC2009_2: C2009.2 R2003.2 U2002.3(+)
NetC2010_2: C2010.2 U2001.3(FLT1)
NetC2017_1: C2017.1 U2003.14(FLT4)
NetC2018_1: C2018.1 U2003.16(FLT2)
NetC2021_2: C2021.2 U2003.1(FLT3)
NetC2022_1: C2022.1 R2025.1 R2032.2 R2033.2
NetC2022_2: C2022.2 U2003.2(RFIN)
NetC2025_2: C2025.2 R2026.2 U2004.3(+)
NetC2026_2: C2026.2 U2003.3(FLT1)
NetR2002_1: R2002.1 R2006.2 U2002.5(+)
NetR2007_2: R2007.2 R2017.2 U2002.7
NetR2008_1: R2008.1 R2019.2 U2002.1
NetR2012_2: R2012.2 R2013.1 R2014.2
NetR2013_2: R2013.2 R2017.1 U2002.6(-)
NetR2015_2: R2015.2 U2001.4(ENBL)
NetR2018_2: R2018.2 R2019.1 U2002.2(-)
NetR2021_2: R2021.2 R2023.2 U2004.5(+)
NetR2024_2: R2024.2 R2036.2 U2004.7
NetR2028_2: R2028.2 R2029.1 R2034.2
NetR2029_2: R2029.2 R2036.1 U2004.6(-)
NetR2030_1: R2030.1 R2038.2 U2004.1
NetR2035_2: R2035.2 U2003.4(ENBL)
NetR2037_2: R2037.2 R2038.1 U2004.2(-)

Not connected (* = marked no-connect by the designer): U2001 6(NC)* 7(NC)* 8(NC)* 12(NC)* 13(NC)*; U2003 6(NC)* 7(NC)* 8(NC)* 12(NC) 13(NC)*

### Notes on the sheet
- (near C2001) FLT1,FLT2,FL3  引脚上电容针对包络检波输出 低通滤波；FLT4引脚电容针对均方根检波输出低通滤波
  转折频率（增益下降3dB的频率）：f，则各引脚电容为：
  CFLT1：1/(2Π×f×10000)-5pF，5pF对饮3.2MHz转折频率，当使用频率小于32MHz才有添加电容必要
  CFLT2：1/(2Π×f×400)-0.4pF，0.4pF对应1GHz转折频率，较高频率无使用必要
  CFLT3：1/(2Π×f×250)-0.8pF，0.8pF对应800MHz转折频率，高频率无使用必要
  CFLT4：1/(2Π×f×400)-20pF，20pF对应20MHz转折频率，RMS滤波电容的大小对RMS精度有直接影响。对于大多数高精度检波，RMS滤波器转折频率应足够低，以便滤除大部分调制内容。为此，转折频率应显著低于被测信号的带宽。较大的值不会进一步提高RMS精度，但可降低VRMS上的输出噪声，代价是上升和下降时间延长。
- (near C2001) 0603
- (near C2002) 0603
- 正向检波输入
- (near U2001) Vule open is not mounted,for reserved.
- (near C2015) 0603
- (near C2016) 0603
- (near C2018) 0603
- (near C2017) 0603
- 反向检波输入
- (near U2003) 0603
- (near R2035) 0603
- (near C2026) 0603
- 1.3GHz-5.5/8.2kW 功放接口板
- WS7.820.415.V01
- 3/5
- V01
- qyj

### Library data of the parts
C2001 C2003 C2005 C2009 C2011 C2012 C2015 C2017 C2019 C2023 C2025 C2027 = 0.1uF贴片电容: as C1 on sheet 1-MCU
C2002 C2016 = 1000pF贴片电容: 贴片电容_100pF±10%,50V,0603
C2004 C2018 = 10pF贴片电容: GRM1885C1H390JA01D_39pF±5%,50V,0603; code: 01010157
C2006 C2020 = 10uF贴片电容: 贴片电容_GRM21BR61A106KE19L_10uF±10%,10V,0805; code: 01010036
C2007 C2021 = 10pF贴片电容: 贴片电容_GRM1885C1H680JA01D_0603,68PF,50V,±5％,COG; MPN: Murata; code: 01010034
C2008 C2022 = 100pF贴片电容: 贴片电容_GRM2165C1H101JA01D_100pF±5%,50V,0805; code: 01010043
C2010 C2026 = 1000pF贴片电容: as C36 on sheet 2-RJ45
C2013 C2028 = 10uF贴片电容: as C9 on sheet 1-MCU
C2014 C2024 = 10uF贴片电容: code: 01010037
R2002 R2006 R2013 R2017 R2021 R2023 R2029 R2036 = 430Ω贴片电阻: code: 01020118
R2003 R2026 = 1K贴片电阻: 贴片电阻_1K±5%,0603; code: 01020082
R2004 R2025 = 56Ω贴片电阻: 贴片电阻_1206,180Ω,±5％
R2005 R2020 = 0Ω贴片电阻: 0603,7.87KΩ,±1％; code: 01020010
R2007 R2008 R2024 R2030 = 10K贴片电阻: 贴片电阻_1K±5%,0603
R2009 R2010 R2031 R2032 = 56Ω贴片电阻: 贴片电阻_68Ω±5%,1206
R2011 R2033 = 75Ω贴片电阻: 贴片电阻_75Ω±5%,0805; code: 01020068
R2012 R2014 R2019 R2028 R2034 R2038 = 0Ω贴片电阻: 贴片电阻_0Ω±5%,0603; code: 01020010
R2015 R2035 = 4.7K贴片电阻: 贴片电阻_4.7K±5%,0603; code: 01020012
R2016 R2027 = 0Ω贴片电阻: 0603,2.2KΩ,±1％; code: 01020010
R2018 R2037 = 0Ω贴片电阻
SMA2001 SMA2002 = SMA-50KFD-4: 射频同轴连接器_SMA-KFD-4; code: 03100009
U2001 U2003 = ADL5511ACPZ: 检波器_ADL5511ACPZ_DC~6GHz,LFCSP16; code: 01060108
U2002 = OP284: Maker: TI; code: 01060201
U2004 = LM358: 运算放大器_LM358_SOIC8; Maker: MOTOROLA; code: 01060025

## Sheet 4-POWER.SchDoc
size A3
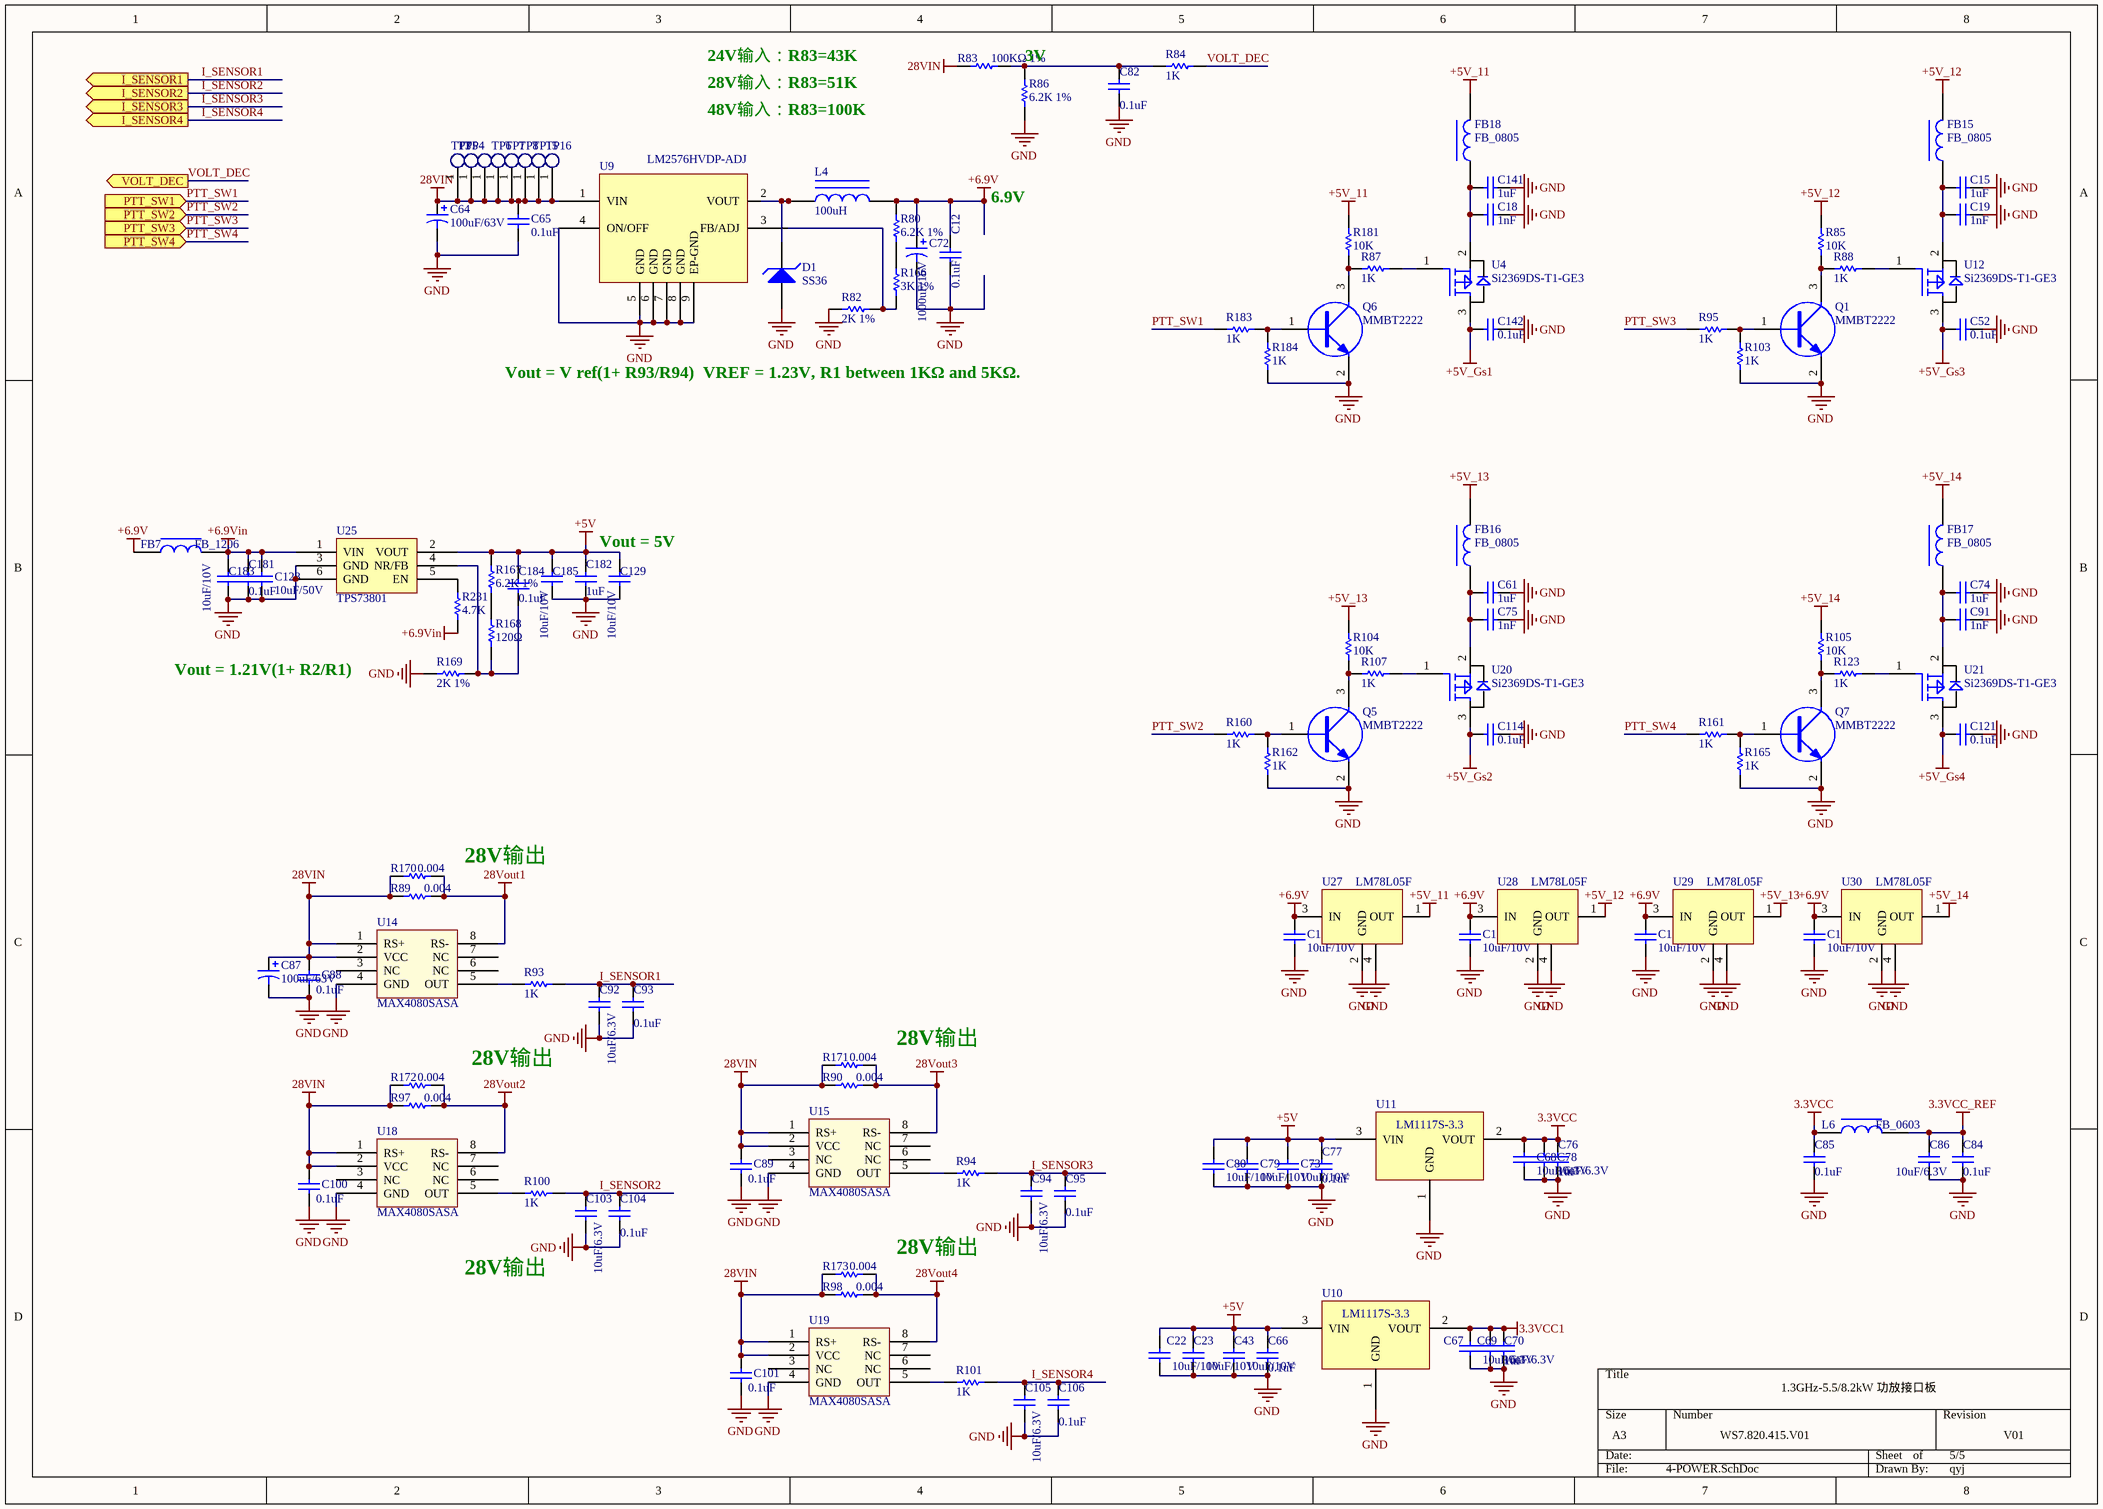
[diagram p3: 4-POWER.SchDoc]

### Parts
C12  0.1uF  [C0603]
C15  1uF  [C0603]
C18  1nF  [C0603]
C19  1nF  [C0603]
C22  10uF/10V  [C0805]
C23  10uF/10V  [C0805]
C43  10uF/10V  [C0805]
C52  0.1uF  [C0603]
C61  1uF  [C0603]
C64  100uF/63V  [ECAP2SM_10R4x10R4]
C65  0.1uF  [C0603]
C66  0.1uF  [C0603]
C67  10uF/6.3V  [C0603]
C68  10uF/6.3V  [C0603]
C69  10uF/6.3V  [C0603]
C70  1uF  [C0603]
C72  1000uF/16V  [ECAP2SM_10R4x10R4]
C73  10uF/10V  [C0805]
C74  1uF  [C0603]
C75  1nF  [C0603]
C76  1uF  [C0603]
C77  0.1uF  [C0603]
C78  10uF/6.3V  [C0603]
C79  10uF/10V  [C0805]
C80  10uF/10V  [C0805]
C82  0.1uF  [C0603]
C84  0.1uF  [C0603]
C85  0.1uF  [C0603]
C86  10uF/6.3V  [C0603]
C87  100uF/63V  [ECAP2SM_10R4x10R4]
C88  0.1uF  [C0603]
C89  0.1uF  [C0603]
C91  1nF  [C0603]
C92  10uF/6.3V  [C0603]
C93  0.1uF  [C0603]
C94  10uF/6.3V  [C0603]
C95  0.1uF  [C0603]
C100  0.1uF  [C0603]
C101  0.1uF  [C0603]
C103  10uF/6.3V  [C0603]
C104  0.1uF  [C0603]
C105  10uF/6.3V  [C0603]
C106  0.1uF  [C0603]
C114  0.1uF  [C0603]
C121  0.1uF  [C0603]
C128  10uF/50V  [C1210]
C129  10uF/10V  [C0805]
C132  10uF/10V  [C0805]
C133  10uF/10V  [C0805]
C134  10uF/10V  [C0805]
C135  10uF/10V  [C0805]
C141  1uF  [C0603]
C142  0.1uF  [C0603]
C181  0.1uF  [C0603]
C182  1uF  [C0603]
C183  10uF/10V  [C0805]
C184  0.1uF  [C0603]
C185  10uF/10V  [C0805]
D1  SS36  [DO-214AC]
FB7  FB_1206  [L1206]
FB15  FB_0805  [L0805]
FB16  FB_0805  [L0805]
FB17  FB_0805  [L0805]
FB18  FB_0805  [L0805]
L4  100uH  [PL2SM-12R5x12R5]
L6  FB_0603  [L0603]
Q1  MMBT2222  [SOT23-3]
Q5  MMBT2222  [SOT23-3]
Q6  MMBT2222  [SOT23-3]
Q7  MMBT2222  [SOT23-3]
R80  6.2K 1%  [R0603]
R82  2K 1%  [R0603]
R83  100KΩ 1%  [R0603]
R84  1K  [R0603]
R85  10K  [R0603]
R86  6.2K 1%  [R0603]
R87  1K  [R0603]
R88  1K  [R0603]
R89  0.004  [R2512]
R90  0.004  [R2512]
R93  1K  [R0603]
R94  1K  [R0603]
R95  1K  [R0603]
R97  0.004  [R2512]
R98  0.004  [R2512]
R100  1K  [R0603]
R101  1K  [R0603]
R103  1K  [R0603]
R104  10K  [R0603]
R105  10K  [R0603]
R107  1K  [R0603]
R123  1K  [R0603]
R160  1K  [R0603]
R161  1K  [R0603]
R162  1K  [R0603]
R165  1K  [R0603]
R166  3K 1%  [R0603]
R167  6.2K 1%  [R0603]
R168  120Ω  [R0603]
R169  2K 1%  [R0603]
R170  0.004  [R2512]
R171  0.004  [R2512]
R172  0.004  [R2512]
R173  0.004  [R2512]
R181  10K  [R0603]
R183  1K  [R0603]
R184  1K  [R0603]
R231  4.7K  [R0603]
TP3  RTF-76-006-M4-S  [FC-M4]  (value not drawn)  (no BOM)
TP4  RTF-76-006-M4-S  [FC-M4]  (value not drawn)  (no BOM)
TP5  RTF-76-006-M4-S  [FC-M4]  (value not drawn)  (no BOM)
TP6  RTF-76-006-M4-S  [FC-M4]  (value not drawn)  (no BOM)
TP7  RTF-76-006-M4-S  [FC-M4]  (value not drawn)  (no BOM)
TP8  RTF-76-006-M4-S  [FC-M4]  (value not drawn)  (no BOM)
TP15  RTF-76-006-M4-S  [FC-M4]  (value not drawn)  (no BOM)
TP16  RTF-76-006-M4-S  [FC-M4]  (value not drawn)  (no BOM)
U4  Si2369DS-T1-GE3  [SOT23-3]
U9  LM2576HVDP-ADJ  [SOIC8_1R27_3R9x4R9-1]
U10  LM1117S-3.3  [SOT-223]
U11  LM1117S-3.3  [SOT-223]
U12  Si2369DS-T1-GE3  [SOT23-3]
U14  MAX4080SASA  [SOIC8_1R27_3R9x4R9]
U15  MAX4080SASA  [SOIC8_1R27_3R9x4R9]
U18  MAX4080SASA  [SOIC8_1R27_3R9x4R9]
U19  MAX4080SASA  [SOIC8_1R27_3R9x4R9]
U20  Si2369DS-T1-GE3  [SOT23-3]
U21  Si2369DS-T1-GE3  [SOT23-3]
U25  TPS73801  [SOT-223-6]
U27  LM78L05F  [SOT-89]
U28  LM78L05F  [SOT-89]
U29  LM78L05F  [SOT-89]
U30  LM78L05F  [SOT-89]

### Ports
I_SENSOR1 (out), I_SENSOR2 (out), I_SENSOR3 (out), I_SENSOR4 (out), PTT_SW1 (in), PTT_SW2 (in), PTT_SW3 (in), PTT_SW4 (in), VOLT_DEC (out)

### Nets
3.3VCC: C68.2 C76.2 C78.2 C85.2 L6.1 U11.2(VOUT)
3.3VCC1: C67.2 C69.2 C70.2 U10.2(VOUT)
3.3VCC_REF: C84.2 C86.2 L6.2
28VIN: C64.1 C65.2 C87.1 C88.2 C89.2 C100.2 C101.2 R83.1 R89.1 R90.1 R97.1 R98.1 R170.1 R171.1 R172.1 R173.1 TP3.1(TP) TP4.1(TP) TP5.1(TP) TP6.1(TP) TP7.1(TP) TP8.1(TP) TP15.1(TP) TP16.1(TP) U9.1(VIN) U14.1(RS+) U14.2(VCC) U15.1(RS+) U15.2(VCC) U18.1(RS+) U18.2(VCC) U19.1(RS+) U19.2(VCC)
28Vout1: R89.2 R170.2 U14.8(RS-)
28Vout2: R97.2 R172.2 U18.8(RS-)
28Vout3: R90.2 R171.2 U15.8(RS-)
28Vout4: R98.2 R173.2 U19.8(RS-)
+5V: C22.2 C23.2 C43.2 C66.2 C73.2 C77.2 C79.2 C80.2 C129.2 C182.2 C184.2 C185.2 R167.2 U10.3(VIN) U11.3(VIN) U25.2(VOUT)
+5V_11: FB18.2 R181.2 U27.1(OUT)
+5V_12: FB15.2 R85.2 U28.1(OUT)
+5V_13: FB16.2 R104.2 U29.1(OUT)
+5V_14: FB17.2 R105.2 U30.1(OUT)
+5V_Gs1: C142.2 U4.3(D)
+5V_Gs2: C114.2 U20.3(D)
+5V_Gs3: C52.2 U12.3(D)
+5V_Gs4: C121.2 U21.3(D)
+6.9V: C12.2 C72.1 C132.2 C133.2 C134.2 C135.2 FB7.1 L4.2 R80.2 U27.3(IN) U28.3(IN) U29.3(IN) U30.3(IN)
+6.9Vin: C128.2 C181.2 C183.2 FB7.2 R231.2 U25.1(VIN)
GND: C12.1 C15.1 C18.2 C19.2 C22.1 C23.1 C43.1 C52.1 C61.1 C64.2 C65.1 C66.1 C67.1 C68.1 C69.1 C70.1 C72.2 C73.1 C74.1 C75.2 C76.1 C77.1 C78.1 C79.1 C80.1 C82.1 C84.1 C85.1 C86.1 C87.2 C88.1 C89.1 C91.2 C92.1 C93.1 C94.1 C95.1 C100.1 C101.1 C103.1 C104.1 C105.1 C106.1 C114.1 C121.1 C128.1 C129.1 C132.1 C133.1 C134.1 C135.1 C141.1 C142.1 C181.1 C182.1 C183.1 C185.1 D1.1(A) Q1.2(E) Q5.2(E) Q6.2(E) Q7.2(E) R82.2 R86.1 R103.1 R162.1 R165.1 R169.2 R184.1 U9.4(ON/OFF) U9.5(GND) U9.6(GND) U9.7(GND) U9.8(GND) U9.9(EP-GND) U10.1(GND) U11.1(GND) U14.4(GND) U15.4(GND) U18.4(GND) U19.4(GND) U25.3(GND) U25.6(GND) U27.2(GND) U27.4(GND) U28.2(GND) U28.4(GND) U29.2(GND) U29.4(GND) U30.2(GND) U30.4(GND)
I_SENSOR1: C92.2 C93.2 R93.2 ; port I_SENSOR1
I_SENSOR2: C103.2 C104.2 R100.2 ; port I_SENSOR2
I_SENSOR3: C94.2 C95.2 R94.2 ; port I_SENSOR3
I_SENSOR4: C105.2 C106.2 R101.2 ; port I_SENSOR4
PTT_SW1: R183.1 ; port PTT_SW1
PTT_SW2: R160.1 ; port PTT_SW2
PTT_SW3: R95.1 ; port PTT_SW3
PTT_SW4: R161.1 ; port PTT_SW4
VOLT_DEC: R84.1 ; port VOLT_DEC
NetC15_2: C15.2 C19.1 FB15.1 U12.2(S)
NetC18_1: C18.1 C141.2 FB18.1 U4.2(S)
NetC61_2: C61.2 C75.1 FB16.1 U20.2(S)
NetC74_2: C74.2 C91.1 FB17.1 U21.2(S)
NetC82_2: C82.2 R83.2 R84.2 R86.2
NetC184_1: C184.1 R168.1 R169.1 U25.4(NR/FB)
NetD1_2: D1.2(K) L4.1 U9.2(VOUT)
NetQ1_1: Q1.1(B) R95.2 R103.2
NetQ1_3: Q1.3(C) R85.1 R88.1
NetQ5_1: Q5.1(B) R160.2 R162.2
NetQ5_3: Q5.3(C) R104.1 R107.1
NetQ6_1: Q6.1(B) R183.2 R184.2
NetQ6_3: Q6.3(C) R87.1 R181.1
NetQ7_1: Q7.1(B) R161.2 R165.2
NetQ7_3: Q7.3(C) R105.1 R123.1
NetR80_1: R80.1 R166.2
NetR82_1: R82.1 R166.1 U9.3(FB/ADJ)
NetR87_2: R87.2 U4.1(G)
NetR88_2: R88.2 U12.1(G)
NetR93_1: R93.1 U14.5(OUT)
NetR94_1: R94.1 U15.5(OUT)
NetR100_1: R100.1 U18.5(OUT)
NetR101_1: R101.1 U19.5(OUT)
NetR107_2: R107.2 U20.1(G)
NetR123_2: R123.2 U21.1(G)
NetR167_1: R167.1 R168.2
NetR231_1: R231.1 U25.5(EN)

Not connected (* = marked no-connect by the designer): U14 3(NC) 6(NC) 7(NC); U15 3(NC) 6(NC) 7(NC); U18 3(NC) 6(NC) 7(NC); U19 3(NC) 6(NC) 7(NC)

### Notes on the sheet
- 24V输入：R83=43K
- 28V输入：R83=51K
- (near R86) 3V
- 48V输入：R83=100K
- 6.9V
- Vout = V ref(1+ R93/R94)  VREF = 1.23V, R1 between 1KΩ and 5KΩ.
- Vout = 5V
- Vout = 1.21V(1+ R2/R1)
- 28V输出
- 1.3GHz-5.5/8.2kW 功放接口板
- WS7.820.415.V01
- 5/5
- V01
- qyj

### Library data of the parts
C12 C52 C65 C66 C77 C82 C84 C85 C88 C89 C93 C95 C100 C101 C104 C106 C114 C121 C142 C181 C184 = 0.1uF贴片电容: as C1 on sheet 1-MCU
C15 C61 C70 C74 C76 C141 C182 = 1uF贴片电容: 贴片电容_GRM188R61A105KA61D_1uF±10%,10V,0603; code: 01010038
C18 C19 C75 C91 = 1000pF贴片电容: as C36 on sheet 2-RJ45
C22 C23 C43 C73 C79 C80 C129 C132-C135 C183 C185 = 10uF贴片电容: as C2006 on sheet 3-RF
C64 C87 = 100uF/63V: 贴片电解电容_VEJ101M1JTR-1010_100uF/63V,±20%,表贴D10*H10; code: 01080002
C67-C69 C78 C86 C92 C94 C103 C105 = 10uF贴片电容: as C9 on sheet 1-MCU
C72 = 1000uF/16V: 贴片电解电容_VE102M1CTR-1010_1000uF/16V,±20%,表贴10*10; code: 01080003
C128 = 10uF贴片电容: 贴片电容_GRM32ER71H106KA12L_10uF±10%,50V,1210; code: 03030021
D1 = 肖特基整流二极管_SS36: 肖特基整流二极管_SS36_封装SMA,3A/60V; code: 01040003
FB7 = 1206贴片磁珠: 贴片磁珠_30R,6A,1206; code: 0103015
FB15-FB18 = 0805贴片磁珠: 贴片磁珠_600R,0805; code: 01030023
L4 = 100uH贴片功率电感: 贴片功率电感_SLF12575T-101M1R9-PF_100uH±20%,额定电流1.9A,12.5x12.5; code: 01030003
L6 = 0603贴片磁珠: 贴片磁珠_100R,0603; code: 0103016
Q1 Q5-Q7 = MMBT2222: NPN三极管_MMBT2222_表贴SOT23; code: 01050001
R80 R167 = 6.2K贴片电阻: 贴片电阻_6.2K±5%,0603; code: 01020106
R82 R169 = 2K贴片电阻: 贴片电阻_2K±5%,0603; code: 01020086
R83 = 12.4K贴片电阻: 贴片电阻_12.4K±1%,0603; code: 01020125
R84 R87 R88 R93-R95 R100 R101 R103 R107 R123 R160-R162 R165 R183 R184 = 1K贴片电阻: 贴片电阻_1K±5%,0603; code: 01020082
R85 R104 R105 R181 = 10K贴片电阻: 贴片电阻_10K±5%,0603; code: 01020011
R86 = 1.5K贴片电阻: 贴片电阻_1.5K±5%,0603; code: 01020063
R89 R90 R97 R98 R170-R173 = 0.004Ω检流电阻-标准封装: 贴片电阻_LR12DTDSR004_0.004±5%,2W,2512; code: 01020105
R166 = 3K贴片电阻: 贴片电阻_3K±5%,0603; code: 01020065
R168 = 120Ω贴片电阻: 贴片电阻_120Ω±5%,0603; code: 01020112
R231 = 4.7K贴片电阻: 贴片电阻_4.7K±5%,0603; code: 01020012
TP3-TP8 TP15 TP16 = TP2mm: 表贴测试点1mm
U4 U12 U20 U21 = Si2369DS-T1-GE3: P-MOS_Si2369DS-T1-GE3_SOT23; code: 01060087
U9 = LM2576HVDP-ADJ: 稳压集成电路_LM2576HVDP-ADJ_3A输出,SOIC8; code: 03020005; Maker: HTC
U10 U11 = LM1117S-3.3: LDO_LM1117S-3.3_1A输出,SOT223; code: 01060031
U14 U15 U18 U19 = MAX4080TASA: 电流检测放大器_MAX4080SASA_SOIC8; Maker: MAXIM; code: 01060160
U25 = TPS73701DCQ: LDO_TPS73801_1A输出,SOT223-6; Maker: TI; code: 01060111
U27-U30 = LM78L05F: 功率放大器_LM78L05F_5V输出,100mA输出,SOT89; Maker: HTC; code: 03020026

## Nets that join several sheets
3.3VCC: 1-MCU (26 pins), 2-RJ45 (9 pins), 4-POWER (6 pins)
3.3VCC1: 1-MCU (36 pins), 2-RJ45 (J4.10 J4.12), 4-POWER (C67.2 C69.2 C70.2 U10.2)
3.3VCC_REF: 1-MCU (U2.21), 4-POWER (C84.2 C86.2 L6.2)
+5V: 3-RF (22 pins), 4-POWER (16 pins)
+5V_Gs1: 1-MCU (TP17.1), 4-POWER (C142.2 U4.3)
+5V_Gs2: 1-MCU (TP18.1), 4-POWER (C114.2 U20.3)
+5V_Gs3: 1-MCU (TP19.1), 4-POWER (C52.2 U12.3)
+5V_Gs4: 1-MCU (TP20.1), 4-POWER (C121.2 U21.3)
GND: 1-MCU (66 pins), 2-RJ45 (35 pins), 3-RF (38 pins), 4-POWER (91 pins)
I_SENSOR1: 1-MCU (U2.23), 4-POWER (C92.2 C93.2 R93.2)
I_SENSOR2: 1-MCU (U2.24), 4-POWER (C103.2 C104.2 R100.2)
I_SENSOR3: 1-MCU (U2.25), 4-POWER (C94.2 C95.2 R94.2)
I_SENSOR4: 1-MCU (U2.26), 4-POWER (C105.2 C106.2 R101.2)
LINKLED: 1-MCU (R77.2), 2-RJ45 (R50.2 U5.25)
PTT_SW1: 1-MCU (U2.71), 4-POWER (R183.1)
PTT_SW2: 1-MCU (U2.70), 4-POWER (R160.1)
PTT_SW3: 1-MCU (U2.69), 4-POWER (R95.1)
PTT_SW4: 1-MCU (U2.68), 4-POWER (R161.1)
SPI2_MISO: 1-MCU (R17.2), 2-RJ45 (U5.34)
SPI2_MOSI: 1-MCU (R16.2), 2-RJ45 (U5.35)
SPI2_NSS: 1-MCU (R19.2), 2-RJ45 (R41.1 U5.32)
SPI2_SCK: 1-MCU (R18.2), 2-RJ45 (U5.33)
VENV+: 1-MCU (U2.36), 3-RF (C2012.2 C2014.2 R2007.1)
VENV-: 1-MCU (U2.35), 3-RF (C2023.2 C2024.2 R2024.1)
VOLT_DEC: 1-MCU (U2.18), 4-POWER (R84.1)
VRMS+: 1-MCU (U2.34), 3-RF (C2011.2 C2013.2 R2008.2)
VRMS-: 1-MCU (U2.33), 3-RF (C2027.2 C2028.2 R2030.2)
W5500_INTn: 1-MCU (U2.55), 2-RJ45 (U5.36)
W5500_RSTn: 1-MCU (U2.56), 2-RJ45 (R39.1 U5.37)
